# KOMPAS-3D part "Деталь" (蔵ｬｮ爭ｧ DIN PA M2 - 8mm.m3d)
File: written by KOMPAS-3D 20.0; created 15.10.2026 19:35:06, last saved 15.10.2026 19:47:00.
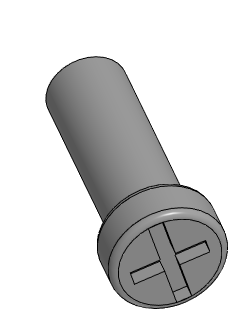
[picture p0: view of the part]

Document properties: Полное имя файла: D:\myProjects\Progect_esp32\box_compas\прочее\Саморез PA M2 - 8mm.m3d

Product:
- Part/product: Деталь
    Масса: 0.000439598
  - Body: Тело 1
      Масса: 0.000433564

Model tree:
1. Эскиз:1
2. Элемент выдавливания:1
     Расстояние 1 = 1.6
3. Эскиз:2  (with: Элемент выдавливания:1)
4. Элемент выдавливания:2
     Расстояние 1 = 8
5. Фаска:1  (with: Элемент выдавливания:2)
     Угол = 45; Длина 1 = 1; Длина 2 = 1
6. Скругление:1  (with: Элемент выдавливания:1)
     Радиус = 0.25
7. Эскиз:3  (with: Элемент выдавливания:1, Скругление:1)
8. Элемент выдавливания:3
     Расстояние 2 = 0.5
